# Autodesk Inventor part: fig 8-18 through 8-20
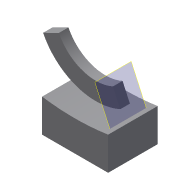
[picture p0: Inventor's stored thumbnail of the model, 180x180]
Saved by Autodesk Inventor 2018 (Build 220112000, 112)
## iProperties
Created: 2010-03
Part Number: fig 8-18 through 8-20
Document SubType Name: Modeling
Designer: CADSoft
Density: 1 g/cm^3
Material: Generic
Appearance: Default
Author: CADSoft
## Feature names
1. Extrusion1
2. Sweep3
## Parameters: d10 = 0, d13 = 0, d14 = 0
